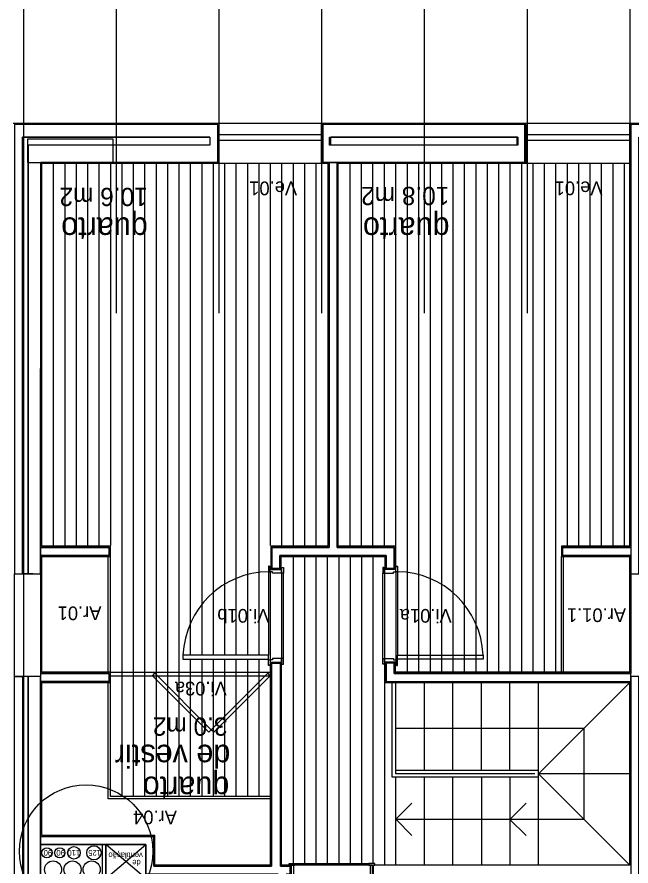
# Model space of a CAD drawing. Extents: x 1278 to 1356, y -253.7 to -224.
# Drawn here: x 1323.82 to 1329.2, y -238.43 to -230.99 of the extents above; entities that cross this region are included whole.
import ezdxf

# ---------------------------------------------------------------- set-up
doc = ezdxf.new("R2010")
doc.units = 0
for name, color, linetype in [('Level 1', 7, 'Continuous'), ('Level 10', 7, 'Continuous'), ('Level 13', 7, 'Continuous'), ('Level 2', 7, 'Continuous'), ('Level 4', 7, 'Continuous'), ('Level 40', 7, 'Continuous'), ('Level 41', 7, 'Continuous'), ('Level 60', 7, 'Continuous'), ('Level 65', 7, 'Continuous'), ('Level 66', 7, 'Continuous'), ('Level 67', 7, 'Continuous'), ('Level 68', 7, 'Continuous'), ('Level 69', 7, 'Continuous'), ('Level 70', 7, 'Continuous'), ('Level 93', 7, 'Continuous')]:
    doc.layers.add(name, color=color, linetype=linetype)

msp = doc.modelspace()

# ---------------------------------------------------------------- linework, layer by layer
at = {"layer": 'Level 1'}
for p, q in [((1325.5818, -231.934), (1325.5818, -232.2657)), ((1326.5018, -232.2657), (1326.5018, -231.934)), ((1328.2818, -231.934), (1328.2818, -232.2657)), ((1323.871, -232.044), (1323.871, -235.8713)), ((1325.5118, -232.044), (1325.5118, -232.1143)), ((1326.5718, -232.114), (1326.5718, -232.044)), ((1328.2118, -232.044), (1328.2118, -232.114)), ((1325.5118, -232.1143), (1323.9218, -232.1143)), ((1324.0318, -242.039), (1324.0317, -232.2657)), ((1325.5818, -232.2657), (1324.0318, -232.2657)), ((1328.2818, -232.2657), (1326.5018, -232.2657)), ((1326.5568, -232.2657), (1326.5568, -235.6407)), ((1326.6268, -235.6407), (1326.6268, -232.2657)), ((1324.6318, -235.6407), (1324.0318, -235.6407)), ((1324.6318, -235.7107), (1324.6318, -235.6407)), ((1326.5568, -235.6407), (1326.0568, -235.6407)), ((1326.0568, -235.6407), (1326.0568, -235.8257)), ((1327.1268, -235.6407), (1326.6268, -235.6407)), ((1327.1268, -235.8257), (1327.1268, -235.6407)), ((1329.2018, -235.6407), (1328.6018, -235.6407)), ((1328.6018, -235.6407), (1328.6018, -235.7107)), ((1324.0318, -235.7107), (1324.6318, -235.7107)), ((1326.1268, -235.7107), (1327.0568, -235.7107)), ((1326.1268, -235.8257), (1326.1268, -235.7107)), ((1327.0568, -235.7107), (1327.0568, -235.8257)), ((1328.6018, -235.7107), (1329.2018, -235.7107)), ((1326.0468, -235.8257), (1326.1368, -235.8257)), ((1327.1418, -235.8257), (1327.0468, -235.8257)), ((1326.0418, -236.6557), (1326.1418, -236.6557)), ((1326.0518, -236.6557), (1326.0518, -238.4357)), ((1326.1318, -238.4357), (1326.1318, -236.6557)), ((1327.1368, -236.6557), (1327.0468, -236.6557)), ((1327.0568, -236.6557), (1327.0568, -236.8157)), ((1327.1268, -236.6557), (1327.1268, -236.7457)), ((1323.871, -236.7713), (1323.871, -242.1713)), ((1323.9218, -242.1713), (1323.9218, -236.7713)), ((1324.6318, -236.7457), (1324.0318, -236.7457)), ((1324.0318, -236.8157), (1324.6318, -236.8157)), ((1324.6318, -236.8157), (1324.6318, -236.7457)), ((1327.0568, -236.8157), (1329.2018, -236.8157)), ((1327.1268, -236.7457), (1329.2018, -236.7457)), ((1324.0317, -238.174), (1325.0225, -238.174)), ((1324.0317, -238.244), (1324.9517, -238.244)), ((1324.5717, -238.544), (1324.5717, -238.244)), ((1324.6017, -238.544), (1324.6017, -238.244)), ((1326.2168, -238.5207), (1326.2168, -238.4257)), ((1326.9468, -238.5307), (1326.9468, -238.4257))]:
    msp.add_line(p, q, dxfattribs=at)
for points in [[(1325.0225, -238.4357), (1325.0225, -238.174)], [(1324.9517, -238.244), (1324.9517, -238.499)]]:
    msp.add_lwpolyline(points, dxfattribs=at)
at = {"layer": 'Level 10'}
for p, q in [((1324.1418, -232.2757), (1324.1418, -235.6307)), ((1324.2418, -232.2757), (1324.2418, -235.6307)), ((1324.3418, -232.2757), (1324.3418, -235.6307)), ((1324.4418, -232.2757), (1324.4418, -235.6307)), ((1324.5418, -232.2757), (1324.5418, -235.6307)), ((1324.6418, -232.2757), (1324.6418, -235.6257)), ((1324.7418, -232.2757), (1324.7418, -237.8257)), ((1324.8418, -232.2757), (1324.8418, -237.8257)), ((1324.9418, -232.2757), (1324.9418, -237.8257)), ((1325.0418, -232.2757), (1325.0418, -237.8257)), ((1325.1418, -232.2757), (1325.1418, -237.8257)), ((1325.2418, -232.2757), (1325.2418, -237.8257)), ((1325.3418, -232.2757), (1325.3418, -236.5857)), ((1325.4418, -232.2757), (1325.4418, -236.5857)), ((1325.5418, -232.2757), (1325.5418, -236.5857)), ((1325.6418, -232.2757), (1325.6418, -236.5857)), ((1325.7418, -232.2757), (1325.7418, -236.5857)), ((1325.8418, -232.2757), (1325.8418, -236.5857)), ((1325.9418, -232.2757), (1325.9418, -236.5857)), ((1326.0418, -232.2757), (1326.0418, -235.6257)), ((1326.1418, -232.2757), (1326.1418, -235.6257)), ((1326.2418, -232.2757), (1326.2418, -235.6257)), ((1326.3418, -232.2757), (1326.3418, -235.6257)), ((1326.4418, -232.2757), (1326.4418, -235.6257)), ((1326.7418, -235.6257), (1326.7418, -232.2757)), ((1326.8418, -235.6257), (1326.8418, -232.2757)), ((1326.9418, -235.6257), (1326.9418, -232.2757)), ((1327.0418, -235.6257), (1327.0418, -232.2757)), ((1327.1418, -235.8257), (1327.1418, -232.2757)), ((1327.2418, -232.2757), (1327.2418, -236.7357)), ((1327.3418, -232.2757), (1327.3418, -236.7357)), ((1327.4418, -232.2757), (1327.4418, -236.7357)), ((1327.5418, -232.2757), (1327.5418, -236.7357)), ((1327.6418, -232.2757), (1327.6418, -236.7357)), ((1327.7418, -232.2757), (1327.7418, -236.7357)), ((1327.8418, -232.2757), (1327.8418, -236.7357)), ((1327.9418, -232.2757), (1327.9418, -236.7357)), ((1328.0418, -232.2757), (1328.0418, -236.7357)), ((1328.1418, -232.2757), (1328.1418, -236.7357)), ((1328.2418, -232.2757), (1328.2418, -236.7357)), ((1328.3418, -232.2757), (1328.3418, -236.7357)), ((1328.4418, -232.2757), (1328.4418, -236.7357)), ((1328.5418, -232.2757), (1328.5418, -236.7357)), ((1328.6418, -232.2757), (1328.6418, -235.6257)), ((1328.7418, -232.2757), (1328.7418, -235.6257)), ((1328.8418, -232.2757), (1328.8418, -235.6257)), ((1328.9418, -232.2757), (1328.9418, -235.6257)), ((1329.0418, -232.2757), (1329.0418, -235.6257)), ((1329.1418, -232.2757), (1329.1418, -235.6257)), ((1326.2418, -235.7207), (1326.2418, -238.4107)), ((1326.3418, -235.7207), (1326.3418, -238.4257)), ((1326.4418, -235.7207), (1326.4418, -238.4257)), ((1326.5418, -235.7207), (1326.5418, -238.4257)), ((1326.6418, -235.7207), (1326.6418, -238.4257)), ((1326.7418, -235.7207), (1326.7418, -238.4257)), ((1326.8418, -235.7207), (1326.8418, -238.4257)), ((1326.9418, -235.7207), (1326.9418, -238.4107)), ((1326.0418, -235.8557), (1326.0418, -236.6257)), ((1326.1418, -235.8657), (1326.1418, -236.6157)), ((1327.0418, -235.8657), (1327.0418, -236.6157)), ((1327.1418, -235.8557), (1327.1418, -236.6257)), ((1325.3418, -236.6207), (1325.3418, -237.8257)), ((1325.4418, -236.6207), (1325.4418, -237.8257)), ((1325.5418, -236.6207), (1325.5418, -237.8257)), ((1325.6418, -236.6207), (1325.6418, -237.8257)), ((1325.7418, -236.6207), (1325.7418, -237.8257)), ((1325.8418, -236.6207), (1325.8418, -237.8257)), ((1325.9418, -236.6207), (1325.9418, -237.8257)), ((1327.0418, -236.6557), (1327.0418, -238.4257)), ((1326.9068, -238.4257), (1326.2568, -238.4257))]:
    msp.add_line(p, q, dxfattribs=at)
at = {"layer": 'Level 13'}
for p, q in [((1324.6218, -236.7357), (1324.6218, -235.7207)), ((1324.6418, -236.7357), (1324.6418, -235.7207)), ((1328.5918, -236.7357), (1328.5918, -235.7207)), ((1328.6118, -236.7357), (1328.6118, -235.7207)), ((1326.0268, -235.8057), (1326.0268, -235.8557)), ((1326.0368, -235.8057), (1326.0268, -235.8057)), ((1326.0368, -235.8107), (1326.0368, -235.8057)), ((1326.0418, -235.8107), (1326.0368, -235.8107)), ((1326.0418, -235.8557), (1326.0418, -235.8107)), ((1326.0418, -235.8357), (1326.1418, -235.8357)), ((1326.0418, -235.8557), (1326.0418, -235.8357)), ((1326.1418, -235.8657), (1326.1418, -235.8207)), ((1326.1418, -235.8207), (1326.1468, -235.8207)), ((1326.1418, -235.8357), (1326.1418, -235.8657)), ((1326.1468, -235.8207), (1326.1468, -235.8157)), ((1326.1468, -235.8157), (1326.1568, -235.8157)), ((1326.1568, -235.8157), (1326.1568, -235.8657)), ((1327.0268, -235.8157), (1327.0268, -235.8657)), ((1327.0368, -235.8157), (1327.0268, -235.8157)), ((1327.0368, -235.8207), (1327.0368, -235.8157)), ((1327.0418, -235.8207), (1327.0368, -235.8207)), ((1327.0418, -235.8657), (1327.0418, -235.8207)), ((1327.1418, -235.8357), (1327.0418, -235.8357)), ((1327.0418, -235.8357), (1327.0418, -235.8657)), ((1327.1418, -235.8557), (1327.1418, -235.8107)), ((1327.1418, -235.8107), (1327.1468, -235.8107)), ((1327.1418, -235.8557), (1327.1418, -235.8357)), ((1327.1468, -235.8107), (1327.1468, -235.8057)), ((1327.1468, -235.8057), (1327.1568, -235.8057)), ((1327.1568, -235.8057), (1327.1568, -235.8557)), ((1326.0268, -235.8557), (1326.0418, -235.8557)), ((1326.0618, -235.8557), (1326.0418, -235.8557)), ((1326.0618, -235.8657), (1326.0618, -235.8557)), ((1326.1418, -235.8657), (1326.0618, -235.8657)), ((1326.1568, -235.8657), (1326.1418, -235.8657)), ((1327.0268, -235.8657), (1327.0418, -235.8657)), ((1327.0418, -235.8657), (1327.1218, -235.8657)), ((1327.1218, -235.8657), (1327.1218, -235.8557)), ((1327.1218, -235.8557), (1327.1418, -235.8557)), ((1327.1568, -235.8557), (1327.1418, -235.8557)), ((1326.0268, -236.5857), (1325.2768, -236.5857)), ((1325.2768, -236.5857), (1325.2768, -236.6207)), ((1326.0268, -236.6207), (1326.0268, -236.5857)), ((1327.1568, -236.6207), (1327.1568, -236.5857)), ((1327.1568, -236.5857), (1327.9068, -236.5857)), ((1327.9068, -236.5857), (1327.9068, -236.6207)), ((1325.2768, -236.6207), (1326.0268, -236.6207)), ((1326.0268, -236.6757), (1326.0268, -236.6257)), ((1326.0268, -236.6257), (1326.0418, -236.6257)), ((1326.0618, -236.6257), (1326.0418, -236.6257)), ((1326.0418, -236.6257), (1326.0418, -236.6457)), ((1326.0418, -236.6257), (1326.0418, -236.6707)), ((1326.0418, -236.6457), (1326.1418, -236.6457)), ((1326.1418, -236.6157), (1326.0618, -236.6157)), ((1326.0618, -236.6157), (1326.0618, -236.6257)), ((1326.1418, -236.6457), (1326.1418, -236.6157)), ((1326.1568, -236.6157), (1326.1418, -236.6157)), ((1326.1418, -236.6157), (1326.1418, -236.6607)), ((1326.1418, -236.6607), (1326.1468, -236.6607)), ((1326.1468, -236.6607), (1326.1468, -236.6657)), ((1326.1468, -236.6657), (1326.1568, -236.6657)), ((1326.1568, -236.6657), (1326.1568, -236.6157)), ((1327.0268, -236.6657), (1327.0268, -236.6157)), ((1327.0268, -236.6157), (1327.0418, -236.6157)), ((1327.0368, -236.6657), (1327.0268, -236.6657)), ((1327.0418, -236.6607), (1327.0368, -236.6607)), ((1327.0368, -236.6607), (1327.0368, -236.6657)), ((1327.0418, -236.6157), (1327.0418, -236.6607)), ((1327.0418, -236.6457), (1327.0418, -236.6157)), ((1327.0418, -236.6157), (1327.1218, -236.6157)), ((1327.1418, -236.6457), (1327.0418, -236.6457)), ((1327.1218, -236.6157), (1327.1218, -236.6257)), ((1327.1218, -236.6257), (1327.1418, -236.6257)), ((1327.1418, -236.6257), (1327.1418, -236.6457)), ((1327.1568, -236.6257), (1327.1418, -236.6257)), ((1327.1418, -236.6257), (1327.1418, -236.6707)), ((1327.9068, -236.6207), (1327.1568, -236.6207)), ((1327.1568, -236.6757), (1327.1568, -236.6257)), ((1326.0368, -236.6757), (1326.0268, -236.6757)), ((1326.0418, -236.6707), (1326.0368, -236.6707)), ((1326.0368, -236.6707), (1326.0368, -236.6757)), ((1327.1418, -236.6707), (1327.1468, -236.6707)), ((1327.1468, -236.6707), (1327.1468, -236.6757)), ((1327.1468, -236.6757), (1327.1568, -236.6757)), ((1325.0094, -236.7657), (1325.0306, -236.7445)), ((1325.0094, -236.7657), (1325.5044, -237.2607)), ((1325.0306, -236.7445), (1325.5256, -237.2395)), ((1326.0206, -236.7445), (1325.5256, -237.2395)), ((1326.0418, -236.7657), (1325.5468, -237.2607)), ((1326.0418, -236.7657), (1326.0206, -236.7445)), ((1324.6218, -237.8457), (1324.6218, -236.8257)), ((1324.6418, -237.8257), (1324.6418, -236.8257)), ((1325.5044, -237.2607), (1325.5256, -237.2395)), ((1325.5468, -237.2607), (1325.5256, -237.2395)), ((1326.0418, -237.8457), (1324.6218, -237.8457)), ((1326.0418, -237.8257), (1324.6418, -237.8257)), ((1326.2068, -238.4107), (1326.2568, -238.4107)), ((1326.2068, -238.4257), (1326.2068, -238.4107)), ((1326.2568, -238.4257), (1326.2068, -238.4257)), ((1326.2268, -238.5307), (1326.2268, -238.4257)), ((1326.2268, -238.4257), (1326.2568, -238.4257)), ((1326.2468, -238.4257), (1326.2468, -238.5307)), ((1326.2568, -238.4107), (1326.2568, -238.4257)), ((1326.9568, -238.4107), (1326.9068, -238.4107)), ((1326.9068, -238.4107), (1326.9068, -238.4257)), ((1326.9368, -238.4257), (1326.9068, -238.4257)), ((1326.9068, -238.4257), (1326.9568, -238.4257)), ((1326.9168, -238.4257), (1326.9168, -238.5307)), ((1326.9368, -238.5307), (1326.9368, -238.4257)), ((1326.9568, -238.4257), (1326.9568, -238.4107))]:
    msp.add_line(p, q, dxfattribs=at)
at = {"layer": 'Level 2'}
for p, q in [((1326.4918, -231.924), (1325.5918, -231.924)), ((1329.1918, -231.924), (1328.2918, -231.924)), ((1326.4918, -232.024), (1325.5918, -232.024)), ((1329.1918, -232.024), (1328.2918, -232.024)), ((1326.4918, -232.074), (1325.5918, -232.074)), ((1329.1918, -232.074), (1328.2918, -232.074)), ((1326.4918, -232.2757), (1325.5918, -232.2757)), ((1329.1918, -232.2757), (1328.2918, -232.2757)), ((1327.111, -237.6557), (1327.111, -236.8257)), ((1327.141, -237.6257), (1327.141, -236.8257)), ((1327.3918, -237.5957), (1327.3918, -236.8257)), ((1327.6418, -237.5957), (1327.6418, -236.8257)), ((1327.8918, -237.5957), (1327.8918, -236.8257)), ((1328.1418, -237.5957), (1328.1418, -236.8257)), ((1328.3918, -237.5957), (1328.3918, -236.8257)), ((1328.3918, -237.6257), (1329.1918, -236.8257)), ((1327.1418, -237.2257), (1328.7918, -237.2257)), ((1328.7918, -238.0257), (1328.7918, -237.2257)), ((1328.3918, -237.5957), (1327.1418, -237.5957)), ((1328.3598, -237.6257), (1327.1418, -237.6257)), ((1328.3918, -237.6557), (1328.3918, -237.5957)), ((1329.1918, -237.6257), (1328.3918, -237.6257)), ((1328.3918, -237.6257), (1329.1918, -238.4257)), ((1328.3918, -237.6557), (1327.111, -237.6557)), ((1327.1418, -238.424), (1327.1418, -237.6557)), ((1327.3918, -238.424), (1327.3918, -237.654)), ((1327.6418, -238.424), (1327.6418, -237.654)), ((1327.8918, -237.654), (1327.8918, -238.424)), ((1328.1418, -237.654), (1328.1418, -238.424)), ((1328.3918, -238.4257), (1328.3918, -237.6557)), ((1327.2832, -237.8826), (1327.1418, -238.024)), ((1328.2832, -237.8843), (1328.1418, -238.0257)), ((1327.2832, -238.1654), (1327.1418, -238.024)), ((1328.2832, -238.1672), (1328.1418, -238.0257)), ((1328.7918, -238.0257), (1328.1418, -238.0257))]:
    msp.add_line(p, q, dxfattribs=at)
at = {"layer": 'Level 4'}
for p, q in [((1326.0268, -235.8557), (1326.0268, -236.5857)), ((1326.1568, -236.6157), (1326.1568, -235.8657)), ((1327.0268, -236.6157), (1327.0268, -235.8657)), ((1327.1568, -235.8557), (1327.1568, -236.5857)), ((1324.6418, -236.7357), (1326.0418, -236.7357)), ((1324.6418, -236.7657), (1326.0418, -236.7657)), ((1326.2568, -238.4107), (1326.9068, -238.4107))]:
    msp.add_line(p, q, dxfattribs=at)
for centre, start_param, end_param in [((1326.0268, -236.6189), 3.141593, 4.668897), ((1327.1568, -236.6189), 1.614288, 3.141593)]:
    msp.add_ellipse(centre, major_axis=(0, -0.7632), ratio=0.982661, start_param=start_param, end_param=end_param, dxfattribs=at)
at = {"layer": 'Level 41'}
for p, q in [((1324.9518, -238.544), (1324.6018, -238.244)), ((1324.6018, -238.544), (1324.9518, -238.244))]:
    msp.add_line(p, q, dxfattribs=at)
for centre, radius in [((1324.0865, -238.3185), 0.045), ((1324.1985, -238.3185), 0.045), ((1324.3225, -238.3185), 0.055), ((1324.4974, -238.3185), 0.0625), ((1324.14, -238.4644), 0.075), ((1324.3102, -238.4644), 0.075), ((1324.4782, -238.4644), 0.075)]:
    msp.add_circle(centre, radius, dxfattribs=at)
at = {"layer": 'Level 65'}
for p, q in [((1325.5918, -231.924), (1323.791, -231.924)), ((1325.5918, -231.924), (1325.5918, -232.2757)), ((1326.4918, -232.2757), (1326.4918, -231.924)), ((1328.2918, -231.924), (1326.4918, -231.924)), ((1328.2918, -231.924), (1328.2918, -232.2757)), ((1330.9925, -231.924), (1329.1918, -231.924)), ((1329.1918, -235.6307), (1329.1918, -231.924)), ((1325.5918, -232.2757), (1324.0418, -232.2757)), ((1324.0418, -235.6307), (1324.0418, -232.2757)), ((1326.5468, -232.2757), (1326.4918, -232.2757)), ((1326.5468, -232.2757), (1326.5468, -235.6307)), ((1326.6368, -235.6307), (1326.6368, -232.2757)), ((1328.2918, -232.2757), (1326.6368, -232.2757)), ((1324.6418, -235.6307), (1324.0418, -235.6307)), ((1324.6418, -235.7207), (1324.6418, -235.6307)), ((1326.5468, -235.6307), (1326.0468, -235.6307)), ((1326.0468, -235.6307), (1326.0468, -235.8257)), ((1327.1368, -235.6307), (1326.6368, -235.6307)), ((1327.1368, -235.6307), (1327.1368, -235.8257)), ((1329.1918, -235.6307), (1328.5918, -235.6307)), ((1328.5918, -235.6307), (1328.5918, -235.7207)), ((1324.0418, -236.7357), (1324.0418, -235.7207)), ((1324.0418, -235.7207), (1324.6418, -235.7207)), ((1326.1368, -235.8257), (1326.1368, -235.7207)), ((1326.1368, -235.7207), (1327.0468, -235.7207)), ((1327.0468, -235.7207), (1327.0468, -235.8257)), ((1328.5918, -235.7207), (1329.1918, -235.7207)), ((1329.1918, -236.7357), (1329.1918, -235.7207)), ((1329.1918, -236.7357), (1329.1918, -235.7207)), ((1326.0418, -236.6557), (1326.0418, -238.4257)), ((1326.1418, -238.4257), (1326.1418, -236.6557)), ((1327.0468, -236.6557), (1327.0468, -236.8257)), ((1327.1368, -236.6557), (1327.1368, -236.7357)), ((1324.6418, -236.7357), (1324.0418, -236.7357)), ((1324.6418, -236.8257), (1324.6418, -236.7357)), ((1329.1918, -236.7357), (1327.1368, -236.7357)), ((1324.0418, -236.8257), (1324.6418, -236.8257)), ((1327.0468, -236.8257), (1329.1918, -236.8257)), ((1329.1918, -238.4257), (1329.1918, -236.8257)), ((1329.1918, -238.4257), (1329.1918, -236.8257)), ((1324.0418, -238.164), (1325.0325, -238.164)), ((1326.0418, -238.4257), (1325.0325, -238.4257)), ((1326.2168, -238.4257), (1326.1418, -238.4257)), ((1329.1918, -238.4257), (1326.9468, -238.4257))]:
    msp.add_line(p, q, dxfattribs=at)
for points in [[(1324.0418, -238.164), (1324.0418, -236.8257)], [(1325.0325, -238.4257), (1325.0325, -238.164)]]:
    msp.add_lwpolyline(points, dxfattribs=at)
at = {"layer": 'Level 66'}
for p, q in [((1325.5818, -231.934), (1323.801, -231.934)), ((1328.2718, -231.934), (1326.4918, -231.934)), ((1326.4918, -231.934), (1326.4918, -232.2657)), ((1328.2818, -231.934), (1326.5018, -231.934)), ((1328.2718, -232.2657), (1328.2718, -231.934)), ((1330.9825, -231.934), (1329.2018, -231.934)), ((1329.2018, -231.934), (1329.2018, -235.6407)), ((1325.5118, -232.044), (1323.871, -232.044)), ((1326.5618, -232.114), (1326.5618, -232.044)), ((1326.5618, -232.044), (1328.2018, -232.044)), ((1328.2118, -232.044), (1326.5718, -232.044)), ((1328.2018, -232.044), (1328.2018, -232.114)), ((1323.9218, -235.8713), (1323.9218, -232.1143)), ((1328.2018, -232.114), (1326.5618, -232.114)), ((1328.2118, -232.114), (1326.5718, -232.114)), ((1326.4918, -232.2657), (1328.2718, -232.2657)), ((1329.2018, -235.7107), (1329.2018, -236.7457)), ((1323.9618, -235.8713), (1323.871, -235.8713)), ((1329.2018, -236.8157), (1329.2018, -238.4357))]:
    msp.add_line(p, q, dxfattribs=at)
for points in [[(1324.6668, -232.0639), (1323.9168, -232.0639), (1323.9168, -232.2657), (1324.6668, -232.2657)], [(1323.801, -235.8713), (1324.031, -235.8713), (1324.031, -236.7713), (1323.801, -236.7713)], [(1329.2018, -235.8713), (1329.4318, -235.8713), (1329.4318, -236.7713), (1329.2018, -236.7713)]]:
    msp.add_lwpolyline(points, close=True, dxfattribs=at)
at = {"layer": 'Level 67'}
for points in [[(1323.871, -235.8713), (1323.871, -232.044), (1325.5118, -232.044), (1325.5118, -232.1143), (1323.9218, -232.1143), (1323.9218, -235.8713), (1324.031, -235.8713), (1324.0317, -232.2657), (1325.5818, -232.2657), (1325.5818, -231.934), (1323.801, -231.934), (1323.801, -235.8713)], [(1327.1268, -235.6407), (1327.1268, -235.8257), (1327.0568, -235.8257), (1327.0568, -235.7107), (1326.1268, -235.7107), (1326.1268, -235.8257), (1326.0568, -235.8257), (1326.0568, -235.6407), (1326.5568, -235.6407), (1326.5568, -232.2657), (1326.5018, -232.2657), (1326.5018, -231.934), (1326.5018, -232.2657), (1326.6268, -232.2657), (1326.6268, -235.6407), (1327.1268, -235.6407)], [(1330.9825, -232.2657), (1330.9825, -231.934), (1329.2018, -231.934), (1329.2018, -235.8713), (1329.2718, -235.8713), (1329.2718, -232.044), (1330.9125, -232.044), (1330.9125, -232.1143), (1330.0668, -232.1143), (1330.0668, -232.2657)], [(1324.6318, -235.6407), (1324.6318, -235.7107), (1324.0317, -235.7107), (1324.0317, -235.6407)], [(1329.2018, -235.6407), (1329.2018, -235.7107), (1328.6018, -235.7107), (1328.6018, -235.6407)], [(1329.2017, -240.234), (1329.2017, -240.304), (1327.1117, -240.304), (1327.1117, -239.4057), (1326.1117, -239.4057), (1326.1117, -238.5057), (1324.9517, -238.5057), (1324.9517, -238.244), (1324.0317, -238.244), (1324.0317, -238.174), (1325.0225, -238.174), (1325.0225, -238.4357), (1326.0517, -238.4357), (1326.0517, -236.6557), (1326.1317, -236.6557), (1326.1317, -238.4357), (1326.2205, -238.4357), (1326.2167, -238.4357), (1326.2167, -238.5057), (1326.1817, -238.5057), (1326.1817, -239.3357), (1327.1817, -239.3357), (1327.1817, -240.234), (1329.2017, -240.234)], [(1329.2018, -236.7457), (1327.1268, -236.7457), (1327.1268, -236.6557), (1327.0568, -236.6557), (1327.0568, -236.8157), (1329.2018, -236.8157)], [(1323.871, -242.1713), (1323.801, -242.1713), (1323.801, -236.7713), (1323.871, -236.7713), (1323.871, -242.1713)], [(1324.031, -242.1713), (1324.0318, -242.1713), (1324.0318, -242.109), (1324.6318, -242.109), (1324.6318, -242.039), (1324.0318, -242.039), (1324.031, -236.7713), (1323.9218, -236.7713), (1323.9218, -242.1713), (1324.0318, -242.1713)], [(1324.6318, -236.7457), (1324.6318, -236.8157), (1324.0318, -236.8157), (1324.0318, -236.7457)], [(1329.2018, -242.1713), (1329.2718, -242.1713), (1329.2718, -236.7713), (1329.2018, -236.7713)], [(1324.6017, -238.244), (1324.6017, -238.544), (1324.5717, -238.544), (1324.5717, -238.244)]]:
    msp.add_lwpolyline(points, close=True, dxfattribs=at)
at = {"layer": 'Level 68'}
msp.add_line((1328.1418, -238.0257), (1327.1418, -238.0257), dxfattribs=at)
at = {"layer": 'Level 69'}
msp.add_circle((1324.4285, -238.3059), 0.5842, dxfattribs=at)
at = {"layer": 'Level 70'}
msp.add_line((1323.884, -250.7923), (1323.884, -229.6198), dxfattribs=at)
at = {"layer": 'Level 93'}
for p, q in [((1324.694, -233.587), (1324.694, -228.3936)), ((1325.594, -233.587), (1325.594, -228.3936)), ((1326.494, -233.587), (1326.494, -228.3936)), ((1327.394, -233.587), (1327.394, -228.3936)), ((1328.294, -233.587), (1328.294, -228.3936)), ((1329.194, -233.587), (1329.194, -228.3936))]:
    msp.add_line(p, q, dxfattribs=at)

# ---------------------------------------------------------------- texts
at = {"layer": 'Level 40'}
for s, rotation, p in [('Ve.01', 180.00001, (1326.2773, -232.4335)), ('Ve.01', 180.00001, (1328.9528, -232.4335)), ('Ar.01', 179.99999, (1324.5634, -236.1586)), ('Vi.01b', 180.00001, (1326.0336, -236.1806)), ('Vi.01a', 180.00001, (1327.6316, -236.1806)), ('Ar.01.1', 179.99999, (1329.1582, -236.1751)), ('Vi.03a', 180.00001, (1325.6615, -236.8188)), ('Ar.04', 179.99999, (1325.2247, -237.9477))]:
    msp.add_text(s, height=0.12, rotation=rotation, dxfattribs=at).set_placement(p)
at = {"layer": 'Level 41'}
for s, p in [('90', (1324.1315, -238.2935)), ('90', (1324.2435, -238.2935)), ('110', (1324.3775, -238.2935)), ('125', (1324.5599, -238.2935)), ('ventilação ', (1324.9258, -238.3155)), (' de ', (1324.9258, -238.3799))]:
    msp.add_text(s, height=0.05, rotation=180, dxfattribs=at).set_placement(p)
at = {"layer": 'Level 60'}
for s, height, p in [('10.6 m2', 0.16, (1324.9692, -232.4888)), ('10.8 m2', 0.16, (1327.6109, -232.4804)), ('quarto', 0.2, (1324.9692, -232.7482)), ('quarto', 0.2, (1327.6122, -232.7482)), ('3.0 m2', 0.16, (1325.668, -237.1316)), ('de vestir', 0.2, (1325.6921, -237.3705)), ('de vestir', 0.2, (1325.6921, -237.3705)), ('quarto', 0.2, (1325.6834, -237.6501))]:
    msp.add_text(s, height=height, rotation=180, dxfattribs=at).set_placement(p)

doc.saveas('drawing.dxf')
